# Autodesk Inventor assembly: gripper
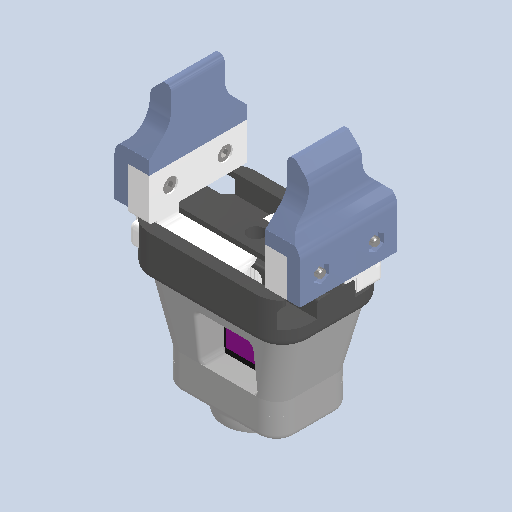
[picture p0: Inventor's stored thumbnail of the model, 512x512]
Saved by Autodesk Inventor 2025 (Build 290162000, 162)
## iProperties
Created: 2023-11
Part Number: gripper
Document SubType Name: Assembly
Designer: Ryzen5700u
Author: Ryzen5700u
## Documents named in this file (12)
- C:\Users\Ryzen5700u\Desktop\scara\Assieme_scara_03\gripper v3.iam
- C:\Users\Ryzen5700u\Desktop\scara\Assieme_scara_03\gripper_rail_base v1.ipt
- C:\Users\Ryzen5700u\Desktop\scara\Assieme_scara_03\gripper_finger v1.ipt
- C:\Users\Ryzen5700u\Desktop\scara\Assieme_scara_03\gripper_base_plate v1.ipt
- C:\Users\Ryzen5700u\Desktop\scara\Assieme_scara_03\MG90S_assieme_disco_ldb2.iam
- C:\Users\Ryzen5700u\Desktop\scara\Assieme_scara_03\MG90S 9g Micro Servo Medium Horn 12 holes.ipt
- C:\Users\Ryzen5700u\Desktop\scara\Assieme_scara_03\blocco_giunto_polso.ipt
- C:\Users\Ryzen5700u\Desktop\scara\Assieme_scara_03\gripper_spur_gear v2.ipt
- C:\Users\Ryzen5700u\Desktop\scara\Assieme_scara_03\dito1.ipt
- C:\Users\Ryzen5700u\Desktop\scara\Assieme_scara_03\AS 1420 - 1973 - M3 x 10.ipt
- C:\Users\Ryzen5700u\Desktop\scara\Assieme_scara_03\BS 4168 - M2,5 x 10(1).ipt
- C:\Users\Ryzen5700u\Desktop\scara\Assieme_scara_03\AS 1427 - M2 x 12(5) I.ipt
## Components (17 placed, 11 different names)
1. gripper_rail_base v1:1
2. gripper_finger v1:1
3. gripper_finger v1:2
4. gripper_base_plate v1:1
5. MG90S_assieme_disco_ldb2:2 [sub-assembly]
6. MG90S 9g Micro Servo Medium Horn 12 holes:1
7. blocco_giunto_polso:1
8. gripper_spur_gear v2:1
9. dito1:1
10. dito1:2
11. AS 1420 - Metrico M3 x 10:1
12. AS 1420 - Metrico M3 x 10:2
13. AS 1420 - Metrico M3 x 10:3
14. AS 1420 - Metrico M3 x 10:4
15. BS 4168 : Parte 1 Vite con esagono incassato - Metrico M2,5 x 10:1
16. AS 1420 - Metrico M3 x 10:7
17. AS 1427 H - Metrico M2 x 12:1
